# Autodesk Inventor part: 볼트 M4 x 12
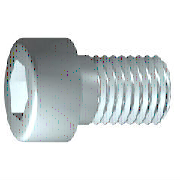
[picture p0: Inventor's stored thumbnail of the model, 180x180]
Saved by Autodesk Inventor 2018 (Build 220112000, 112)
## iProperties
IsCustomPart: 0
Created: 2016-05
Part Number: 볼트 M4 x 12
Material: 강, 연강
Description: 6각머리 태핑 나사
Document SubType Name: Modeling
Standard: KS B 1003
Designer: mduedu
Standards Organization: KS
Language: ko-KR
Size Designation: M 4 x 12
Categories: <MemberInstance><Categories><Category DisplayName="조임쇠" InternalName="e4da775c-781d-43d5-af7c-5136215cf5a6" Mnemonic="FSTN"><Category DisplayName="볼트" InternalN
Density: 1 g/cm^3
Appearance: 연마 - 진회색
Author: mduedu
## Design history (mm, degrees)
sketch "스케치1"
  geometry: L1 (-1, 0)-(12, 0); L2 (12, 0)-(12, 2); L3 (12, 2)-(1.75, 2); L4 (1.75, 2)-(1.32, 2); L5 (1.32, 2)-(0, 2); L6 (0, 2)-(0, 3.5); L7 (0, 3.5)-(-4, 3.5); L8 (-4, 3.5)-(-4, 1.732); L9 (-4, 1.732)-(-2, 1.732); L10 (-2, 1.732)-(-1, 0); L11 (-7.2, 0)-(15.2, 0) reference; L12 (0, -0.7)-(0, 4.2) reference; L13 (1.75, 2)-(0, 2)
  constraints: 22 end point, 6 parallel, 2 collinear, 2 perpendicular, 1 horizontal, 1 point on line
  dimensions: "d1" = 10.25 distance from line of L3.end L2 (= GEL); "d2" = 0.42952 distance of L4.end L3.end (computed from GAL); "d3" = 4 distance between parallel lines of L8 L6 (= KOH); "d4" = 2 distance of L8.end L9.end (= INTI); "d5" = 60 deg angle of L10 L1; "d6" = 4 diameter of L3 L1 (= GD); "d7" = 4 diameter of L5 L1 (= BDM); "d8" = 3.4641 diameter of L9 L1 (= 1.1547 x SW); "d9" = 7 diameter of L7 L1 (= KOD); "d26" = 12 distance between parallel lines of L12 L2 (= NLG)
revolve "본체" sketch "스케치1" stored, may be unused: angle "d10" = 90 deg
sketch "스케치2"
  geometry: L1 (0, -4.9)-(0, 4.9) reference; L2 (-4.9, 0)-(4.9, 0) reference; L3 (1.732, 0)-(0.866, -1.5); L4 (0.866, -1.5)-(-0.866, -1.5); L5 (-0.866, -1.5)-(-1.732, 0); L6 (-1.732, 0)-(-0.866, 1.5); L7 (-0.866, 1.5)-(0.866, 1.5); L8 (0.866, 1.5)-(1.732, 0); 2 further points
  constraints: 12 end point, 1 coincident, 1 horizontal alignment, 1 point on line, 12 other
extrude "슬롯" join sketch "스케치2" stored distance "d11" = 10; taper "d12" = 0 deg
workplane "Work Plane1"
fillet "Fillet2" dims "d30" = 0.1 (= R)
body "Solid1"
fillet "모깎기1" dims "d17" = 0.4 (= RR)
feature "스레드" dims "d13" = 10.25 (= GEL), "d14" = 0
chamfer "모따기1" distance "d15" = 0.42941 (= -0.5 x SPD + 0.5 x GD); stored, may be unused: second distance "d16" = 0.42941 (= GUL), angle "d27" = 45 deg
other parameters: "GD" = 4 (= NND) [user parameter; used in 2 equation terms], "NLG" = 12 [user parameter; used in 1 equation term], "GEL" = 10.25 [user parameter; used in 2 equation terms], "KOD" = 7 [user parameter; used in 1 equation term], "KOH" = 4 [user parameter; used in 1 equation term], "INTI" = 2 [user parameter; used in 1 equation term], "GAL" = 0.42941 (= 0.61345 x PTC) [user parameter; used in 1 equation term], "GUL" = 0.42941 (= 0.61345 x PTC) [user parameter; used in 1 equation term], "BDM" = 4 (= NND) [user parameter; used in 1 equation term], "SW" = 3 [user parameter; used in 2 equation terms], "RR" = 0.4 [user parameter; used in 1 equation term], "SPD" = 3.14117 (= NND - 1.2269 x PTC) [user parameter; used in 1 equation term], "d19" = 0, "d28" = 0, "d29" = 0, "R" = 0.1 [user parameter; used in 1 equation term], "PHH" = 0.2 [user parameter], "GD1" = 3.14117 (= THREADDIA - 1.2269 x PTC) [user parameter], "THREADDIA" = 4 [user parameter; used in 1 equation term], "FAWI" = 45 deg [user parameter], "TPU" = 14.28571 (computed from PTC) [user parameter], "PTC" = 0.7 [user parameter; used in 5 equation terms], "NND" = 4 [user parameter; used in 3 equation terms], "TOA" = 30 deg [user parameter], "E0" = 3.465 (= 1.155 x SW) [user parameter]
